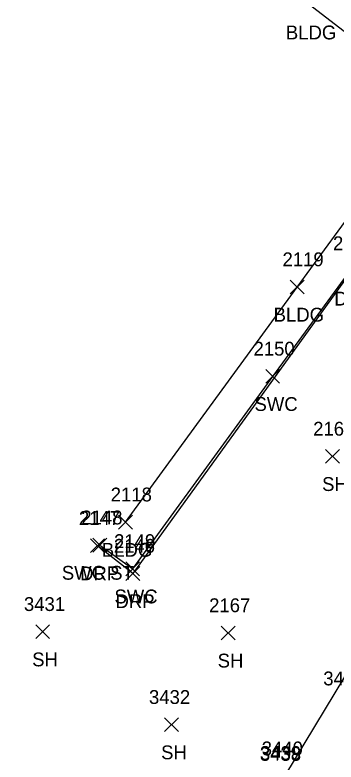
# Model space of a CAD drawing. Extents: x 1634209 to 1639641, y 608564 to 612258.
# Drawn here: x 1639014.2 to 1639060.6, y 611205.4 to 611313.4 of the extents above; entities that cross this region are included whole.
import ezdxf

# ---------------------------------------------------------------- set-up
doc = ezdxf.new("R2010")
doc.units = 0
for name, color, linetype in [('D_I', 7, 'Continuous'), ('DCP', 7, 'Continuous'), ('L_A', 7, 'Continuous'), ('L_I', 7, 'Continuous'), ('L_TIC', 7, 'Continuous'), ('LBC', 7, 'Continuous'), ('R_A', 7, 'Continuous'), ('R_I', 7, 'Continuous'), ('R_TIC', 7, 'Continuous'), ('RDP', 7, 'Continuous'), ('RSW', 7, 'Continuous')]:
    doc.layers.add(name, color=color, linetype=linetype)

msp = doc.modelspace()

# ---------------------------------------------------------------- linework, layer by layer
at = {"layer": 'DCP'}
msp.add_lwpolyline([(1639053.21, 611203.4), (1639105.21, 611289.55)], dxfattribs=at)
at = {"layer": 'L_TIC'}
for points in [[(1639054, 611273.11), (1639056, 611275.11)], [(1639056, 611273.11), (1639054, 611275.11)], [(1639059.1, 611248.62), (1639061.1, 611250.62)], [(1639061.1, 611248.62), (1639059.1, 611250.62)], [(1639029.18, 611239.11), (1639031.18, 611241.11)], [(1639031.18, 611239.11), (1639029.18, 611241.11)], [(1639017.21, 611223.27), (1639019.21, 611225.27)], [(1639019.21, 611223.27), (1639017.21, 611225.27)], [(1639044.01, 611223.1), (1639046.01, 611225.1)], [(1639046.01, 611223.1), (1639044.01, 611225.1)], [(1639035.84, 611209.83), (1639037.84, 611211.83)], [(1639037.84, 611209.83), (1639035.84, 611211.83)]]:
    msp.add_lwpolyline(points, dxfattribs=at)
at = {"layer": 'LBC'}
msp.add_lwpolyline([(1639030.18, 611240.11), (1639055, 611274.11), (1639074.75, 611301.09), (1639056.77, 611314.91), (1639059.81, 611319.01), (1639041.02, 611332.86), (1639050.68, 611345.89), (1639051.33, 611346.8), (1639056.15, 611353.65), (1639047.24, 611360), (1639049.34, 611363.02), (1639049.78, 611363.31), (1639052.47, 611367.11), (1639048.07, 611370.37), (1639042.99, 611363.34), (1639028.13, 611374.15), (1639012.7, 611385.23), (1638995.76, 611397.42), (1638992.44, 611393.67), (1638983.02, 611400.9)], dxfattribs=at)
at = {"layer": 'R_TIC'}
for points in [[(1639050.46, 611260.19), (1639052.46, 611262.19)], [(1639052.46, 611260.19), (1639050.46, 611262.19)], [(1639025.14, 611235.71), (1639027.14, 611237.71)], [(1639027.14, 611235.71), (1639025.14, 611237.71)], [(1639025.49, 611235.79), (1639027.49, 611237.79)], [(1639027.49, 611235.79), (1639025.49, 611237.79)], [(1639030.23, 611232.37), (1639032.23, 611234.37)], [(1639032.23, 611232.37), (1639030.23, 611234.37)], [(1639030.25, 611231.69), (1639032.25, 611233.69)], [(1639032.25, 611231.69), (1639030.25, 611233.69)]]:
    msp.add_lwpolyline(points, dxfattribs=at)
at = {"layer": 'RDP'}
msp.add_lwpolyline([(1639049.99, 611363.21), (1639052.92, 611360.75), (1639053.7, 611361.6), (1639062.63, 611354.26), (1639047.88, 611333.92), (1639066.74, 611319.84), (1639063.67, 611315.97), (1639081.74, 611302.23), (1639062.86, 611276.43), (1639031.25, 611232.69), (1639026.14, 611236.71)], dxfattribs=at)
at = {"layer": 'RSW'}
msp.add_lwpolyline([(1639026.49, 611236.79), (1639031.23, 611233.37), (1639051.46, 611261.19), (1639081.49, 611302.25), (1639063.52, 611315.94), (1639066.43, 611319.95), (1639047.62, 611333.89), (1639054.44, 611343.13), (1639055.17, 611344.17), (1639061.85, 611353.35), (1639049.87, 611363.09)], dxfattribs=at)

# ---------------------------------------------------------------- texts
at = {"layer": 'D_I'}
for s, p in [('3440', (1639049.87, 611206.4)), ('3438', (1639049.6, 611205.61)), ('3439', (1639049.62, 611205.74))]:
    msp.add_text(s, height=2, dxfattribs=at).set_placement(p)
at = {"layer": 'L_A'}
for s, p in [('BLDG', (1639053.36, 611309.91)), ('BLDG', (1639051.59, 611269.11)), ('SH', (1639058.59, 611244.62)), ('BLDG', (1639026.77, 611235.11)), ('SH', (1639016.7, 611219.27)), ('SH', (1639043.5, 611219.1)), ('SH', (1639035.33, 611205.83))]:
    msp.add_text(s, height=2, dxfattribs=at).set_placement(p)
at = {"layer": 'L_I'}
for s, p in [('2119', (1639052.87, 611277.11)), ('2166', (1639057.3, 611252.62)), ('2118', (1639028.05, 611243.11)), ('3431', (1639015.51, 611227.27)), ('2167', (1639042.27, 611227.1)), ('3435', (1639058.76, 611216.52)), ('3432', (1639033.58, 611213.83))]:
    msp.add_text(s, height=2, dxfattribs=at).set_placement(p)
at = {"layer": 'R_A'}
for s, p in [('DRP', (1639060.35, 611271.43)), ('SWC', (1639048.82, 611256.19)), ('SWC ST', (1639020.99, 611231.79)), ('DRP', (1639023.63, 611231.71)), ('SWC', (1639028.59, 611228.37)), ('DRP', (1639028.74, 611227.69))]:
    msp.add_text(s, height=2, dxfattribs=at).set_placement(p)
at = {"layer": 'R_I'}
for s, p in [('2145', (1639060.17, 611279.43)), ('2150', (1639048.68, 611264.19)), ('2147', (1639023.45, 611239.71)), ('2148', (1639023.8, 611239.79)), ('2149', (1639028.53, 611236.37)), ('2146', (1639028.5, 611235.69))]:
    msp.add_text(s, height=2, dxfattribs=at).set_placement(p)

doc.saveas('drawing.dxf')
